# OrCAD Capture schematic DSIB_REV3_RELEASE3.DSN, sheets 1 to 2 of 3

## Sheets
1 Motor Driver: size Custom; rev: 3
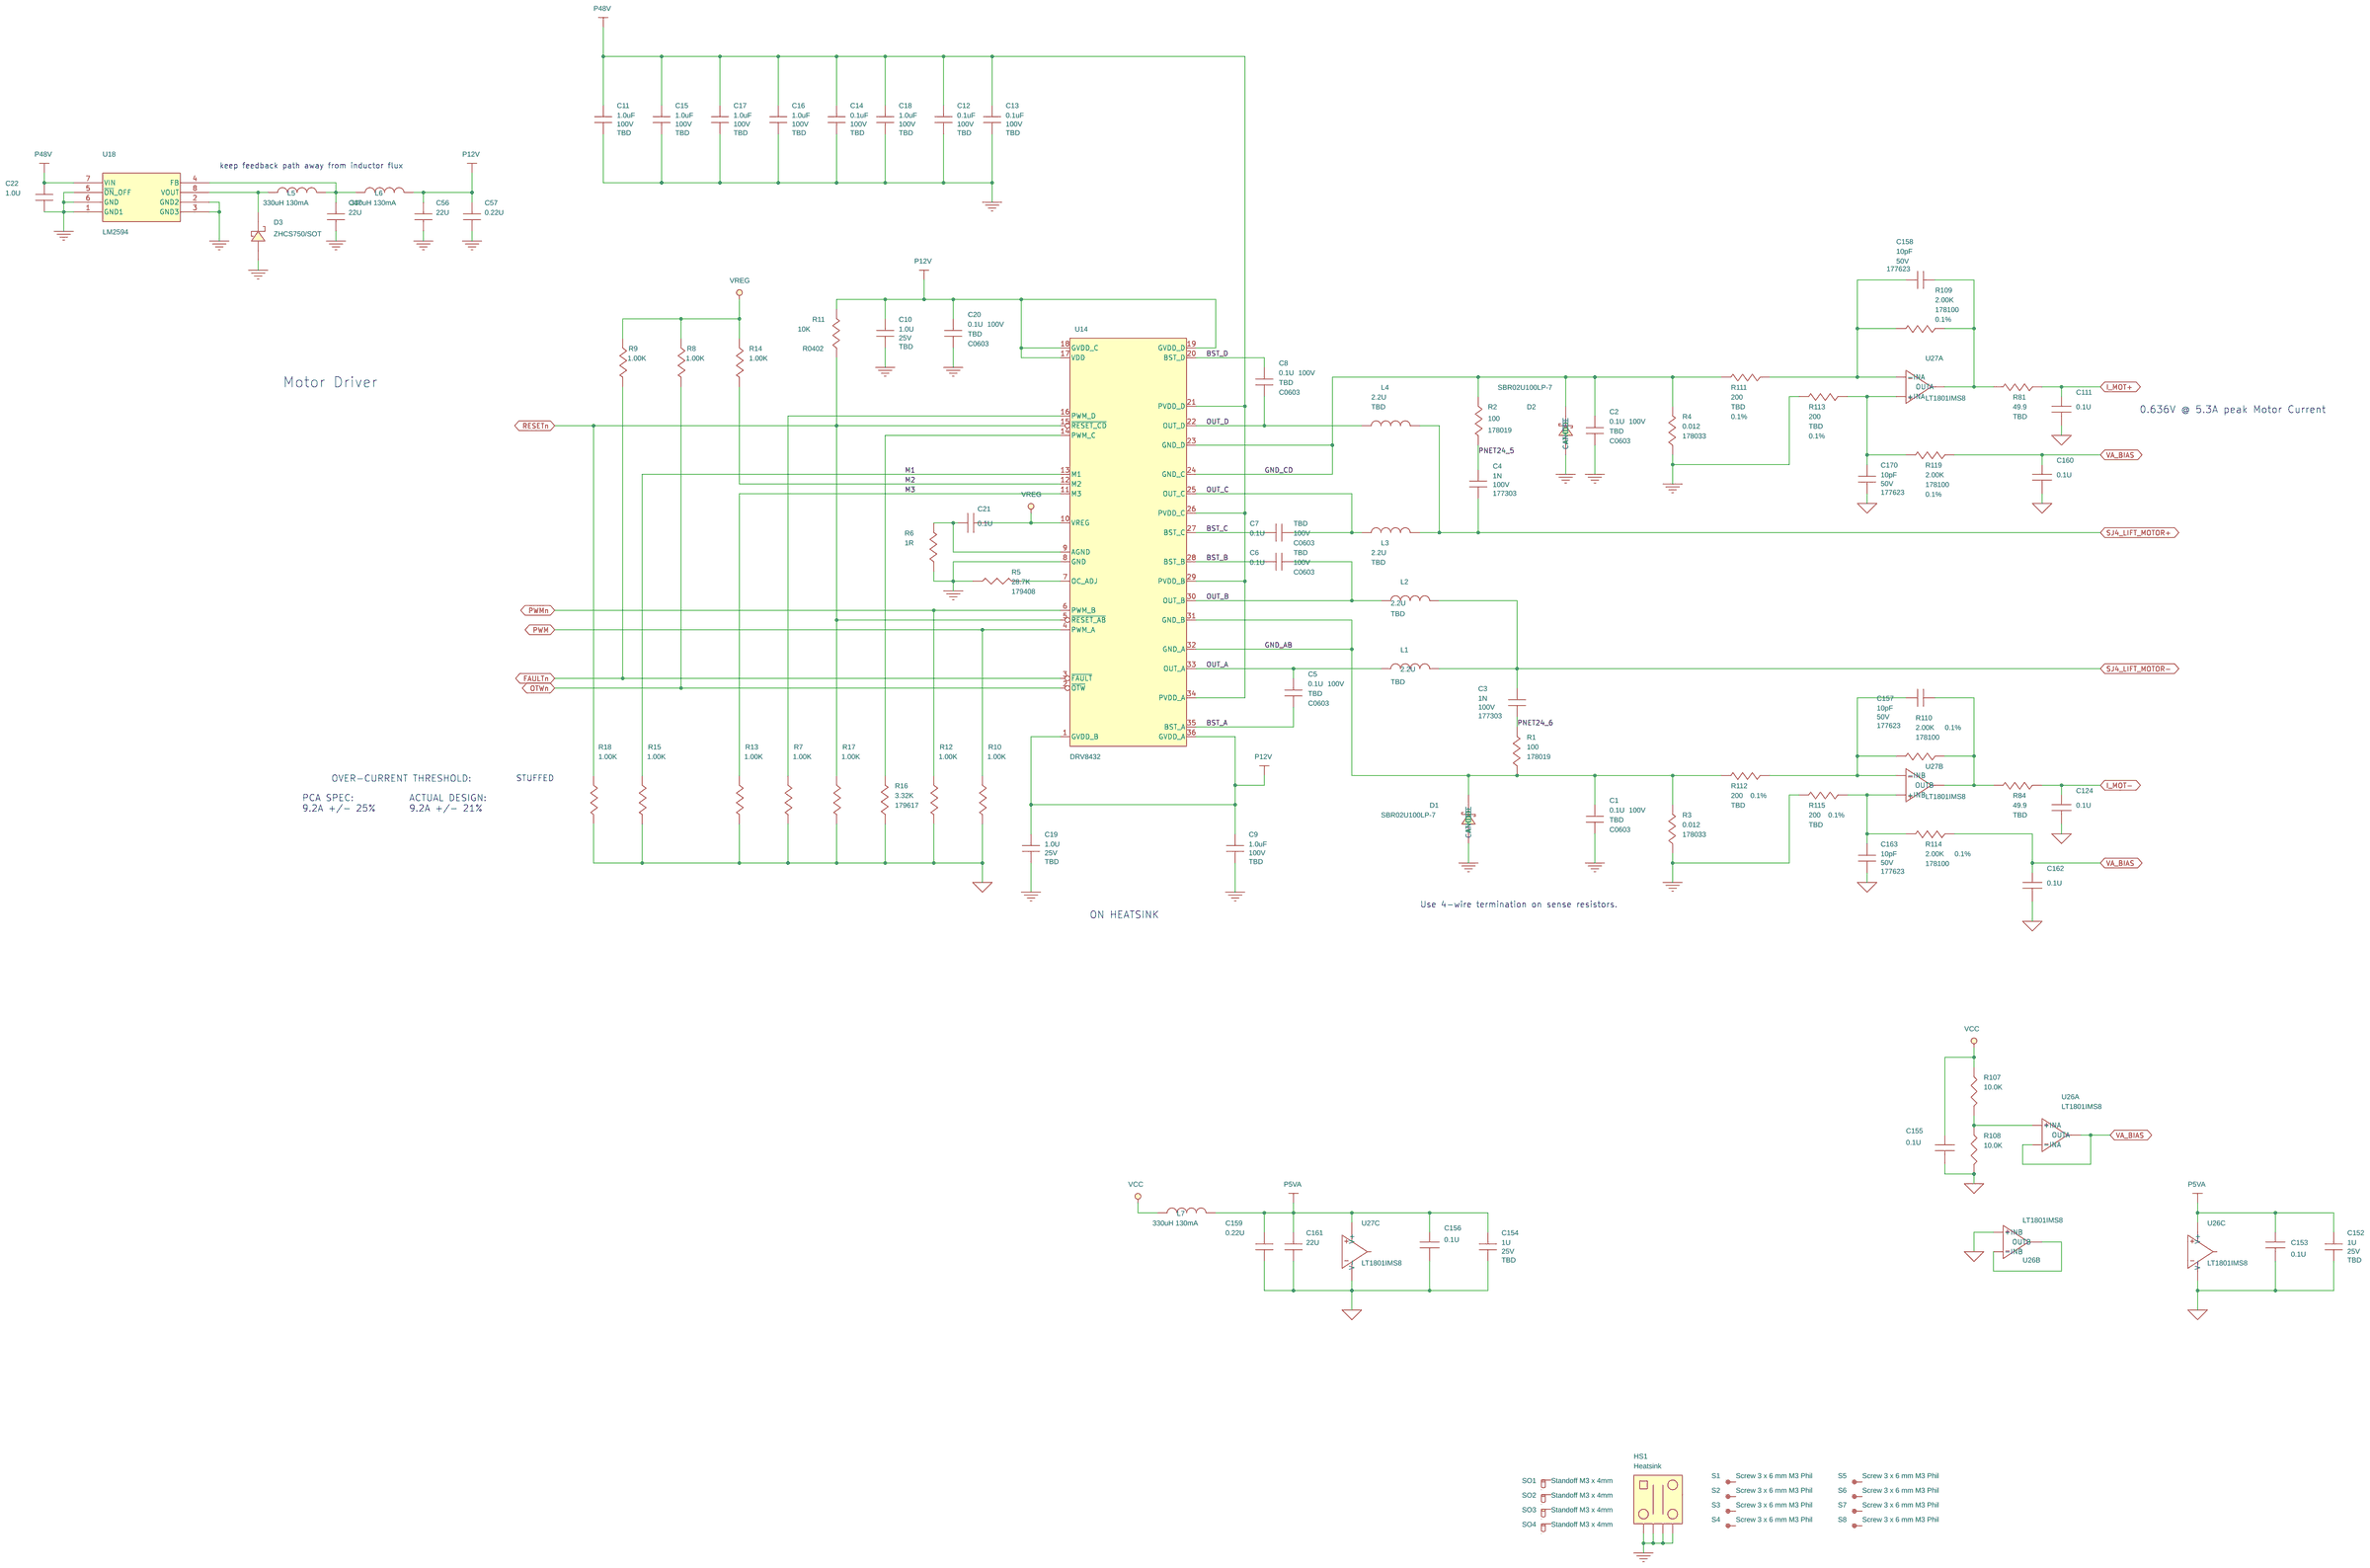
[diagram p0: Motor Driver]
2 Mux: size Custom
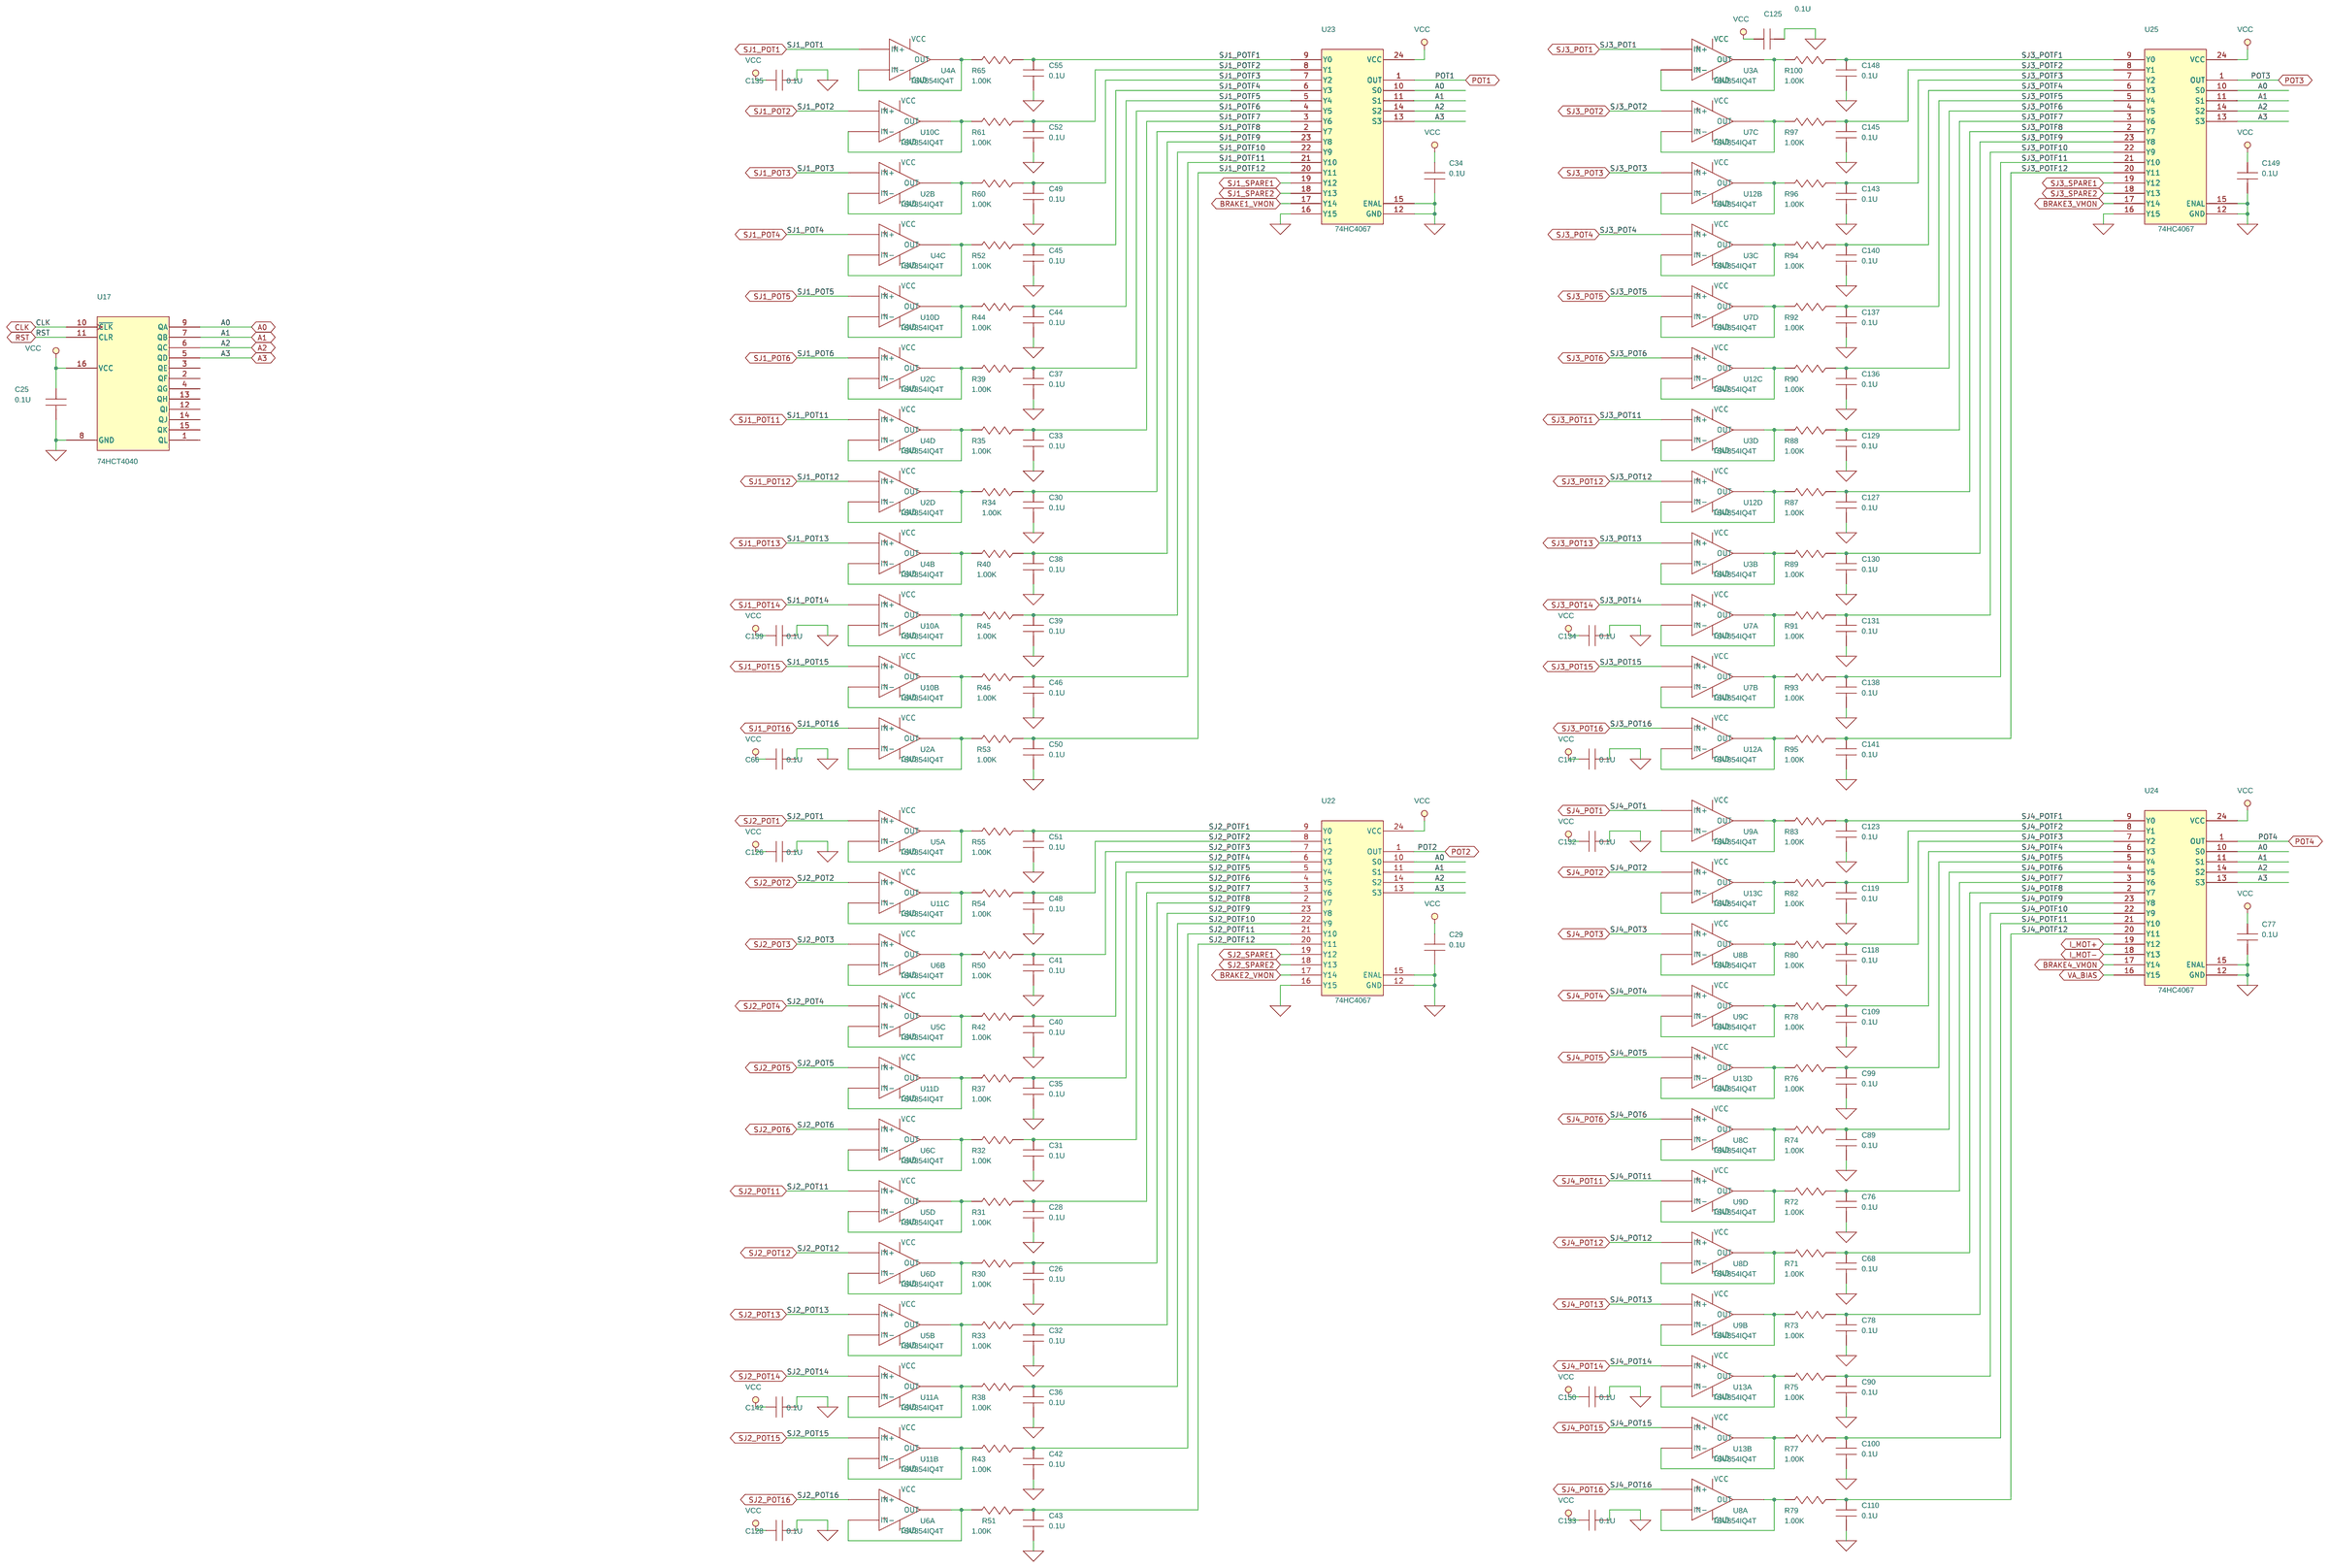
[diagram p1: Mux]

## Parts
sheet Motor Driver
C1  0.1U  [C0603]
C2  0.1U  [C0603]
C3  1N  [C0603]
C4  1N  [C0603]
C5  0.1U  [C0603]
C6  0.1U  [C0603]
C7  0.1U  [C0603]
C8  0.1U  [C0603]
C9  1.0uF  [C0805]
C10  1.0U  [C0603]
C11  1.0uF  [C0805]
C12  0.1uF  [C0805]
C13  0.1uF  [C0805]
C14  0.1uF  [C0805]
C15  1.0uF  [C0805]
C16  1.0uF  [C0805]
C17  1.0uF  [C0805]
C18  1.0uF  [C0805]
C19  1.0U  [C0603]
C20  0.1U  [C0603]
C21  0.1U  [C0402]
C22  1.0U  [C1210]
C47  22U  [C1210]
C56  22U  [C1210]
C57  0.22U  [C0603]
C111  0.1U  [C0402]
C124  0.1U  [C0402]
C152  1U  [CAPC1005_IS0402N]
C153  0.1U  [C0402]
C154  1U  [CAPC1005_IS0402N]
C155  0.1U  [C0402]
C156  0.1U  [C0402]
C157  10pF  [CAPC1005_IS0402N]
C158  10pF  [CAPC1005_IS0402N]
C159  0.22U  [C0603]
C160  0.1U  [C0402]
C161  22U  [C0603]
C162  0.1U  [C0402]
C163  10pF  [CAPC1005_IS0402N]
C170  10pF  [CAPC1005_IS0402N]
D1  SBR02U100LP-7  [DIOS2_173257]
D2  SBR02U100LP-7  [DIOS2_173257]
D3  ZHCS750/SOT  [SM/SOT23_123]
HS1  Heatsink  [HS_VHS45]
L1  2.2U  [INDS2_174036_LARGER]
L2  2.2U  [INDS2_174036_LARGER]
L3  2.2U  [INDS2_174036_LARGER]
L4  2.2U  [INDS2_174036_LARGER]
L5  330uH 130mA  [L4MMX4MM]
L6  330uH 130mA  [L4MMX4MM]
L7  330uH 130mA  [L4MMX4MM]
R1  100  [RESC3225_IS1210N]
R2  100  [RESC3225_IS1210N]
R3  0.012  [RESC3216_IS1206N]
R4  0.012  [RESC3216_IS1206N]
R5  28.7K  [R0402]
R6  1R  [R0402]
R7  1.00K  [RESC1005_IS0402N]
R8  1.00K  [RESC1005_IS0402N]
R9  1.00K  [RESC1005_IS0402N]
R10  1.00K  [RESC1005_IS0402N]
R11  10K  [R0402]
R12  1.00K  [RESC1005_IS0402N]
R13  1.00K  [RESC1005_IS0402N]
R14  1.00K  [RESC1005_IS0402N]
R15  1.00K  [RESC1005_IS0402N]
R16  3.32K  [RESC1005_IS0402N]
R17  1.00K  [RESC1005_IS0402N]
R18  1.00K  [RESC1005_IS0402N]
R81  49.9  [RESC1005_IS0402N]
R84  49.9  [RESC1005_IS0402N]
R107  10.0K  [R0402]
R108  10.0K  [R0402]
R109  2.00K  [RESC1005_IS0402N]
R110  2.00K  [RESC1005_IS0402N]
R111  200  [RESC1005_IS0402N]
R112  200  [RESC1005_IS0402N]
R113  200  [RESC1005_IS0402N]
R114  2.00K  [RESC1005_IS0402N]
R115  200  [RESC1005_IS0402N]
R119  2.00K  [RESC1005_IS0402N]
S1  Screw 3 x 6 mm M3 Phil  [TH825]
S2  Screw 3 x 6 mm M3 Phil  [TH825]
S3  Screw 3 x 6 mm M3 Phil  [TH825]
S4  Screw 3 x 6 mm M3 Phil  [TH825]
S5  Screw 3 x 6 mm M3 Phil  [TH825]
S6  Screw 3 x 6 mm M3 Phil  [TH825]
S7  Screw 3 x 6 mm M3 Phil  [TH825]
S8  Screw 3 x 6 mm M3 Phil  [TH825]
SO1  Standoff M3 x 4mm  [TH40Thou]
SO2  Standoff M3 x 4mm  [TH40Thou]
SO3  Standoff M3 x 4mm  [TH40Thou]
SO4  Standoff M3 x 4mm  [TH40Thou]
U14  DRV8432  [PDSO36]
U18  LM2594  [SO8]
U26  LT1801IMS8  [TSOP65P490_8_D300N]  (sections A,B,C)
U27  LT1801IMS8  [TSOP65P490_8_D300N]  (sections A,B,C)
sheet Mux
C25  0.1U  [C0402]
C26  0.1U  [C0402]
C28  0.1U  [C0402]
C29  0.1U  [C0402]
C30  0.1U  [C0402]
C31  0.1U  [C0402]
C32  0.1U  [C0402]
C33  0.1U  [C0402]
C34  0.1U  [C0402]
C35  0.1U  [C0402]
C36  0.1U  [C0402]
C37  0.1U  [C0402]
C38  0.1U  [C0402]
C39  0.1U  [C0402]
C40  0.1U  [C0402]
C41  0.1U  [C0402]
C42  0.1U  [C0402]
C43  0.1U  [C0402]
C44  0.1U  [C0402]
C45  0.1U  [C0402]
C46  0.1U  [C0402]
C48  0.1U  [C0402]
C49  0.1U  [C0402]
C50  0.1U  [C0402]
C51  0.1U  [C0402]
C52  0.1U  [C0402]
C55  0.1U  [C0402]
C66  0.1U  [C0402]
C68  0.1U  [C0402]
C76  0.1U  [C0402]
C77  0.1U  [C0402]
C78  0.1U  [C0402]
C89  0.1U  [C0402]
C90  0.1U  [C0402]
C99  0.1U  [C0402]
C100  0.1U  [C0402]
C109  0.1U  [C0402]
C110  0.1U  [C0402]
C118  0.1U  [C0402]
C119  0.1U  [C0402]
C123  0.1U  [C0402]
C125  0.1U  [C0402]
C126  0.1U  [C0402]
C127  0.1U  [C0402]
C128  0.1U  [C0402]
C129  0.1U  [C0402]
C130  0.1U  [C0402]
C131  0.1U  [C0402]
C132  0.1U  [C0402]
C133  0.1U  [C0402]
C134  0.1U  [C0402]
C135  0.1U  [C0402]
C136  0.1U  [C0402]
C137  0.1U  [C0402]
C138  0.1U  [C0402]
C139  0.1U  [C0402]
C140  0.1U  [C0402]
C141  0.1U  [C0402]
C142  0.1U  [C0402]
C143  0.1U  [C0402]
C145  0.1U  [C0402]
C147  0.1U  [C0402]
C148  0.1U  [C0402]
C149  0.1U  [C0402]
C150  0.1U  [C0402]
R30  1.00K  [RESC1005_IS0402N]
R31  1.00K  [RESC1005_IS0402N]
R32  1.00K  [RESC1005_IS0402N]
R33  1.00K  [RESC1005_IS0402N]
R34  1.00K  [RESC1005_IS0402N]
R35  1.00K  [RESC1005_IS0402N]
R37  1.00K  [RESC1005_IS0402N]
R38  1.00K  [RESC1005_IS0402N]
R39  1.00K  [RESC1005_IS0402N]
R40  1.00K  [RESC1005_IS0402N]
R42  1.00K  [RESC1005_IS0402N]
R43  1.00K  [RESC1005_IS0402N]
R44  1.00K  [RESC1005_IS0402N]
R45  1.00K  [RESC1005_IS0402N]
R46  1.00K  [RESC1005_IS0402N]
R50  1.00K  [RESC1005_IS0402N]
R51  1.00K  [RESC1005_IS0402N]
R52  1.00K  [RESC1005_IS0402N]
R53  1.00K  [RESC1005_IS0402N]
R54  1.00K  [RESC1005_IS0402N]
R55  1.00K  [RESC1005_IS0402N]
R60  1.00K  [RESC1005_IS0402N]
R61  1.00K  [RESC1005_IS0402N]
R65  1.00K  [RESC1005_IS0402N]
R71  1.00K  [RESC1005_IS0402N]
R72  1.00K  [RESC1005_IS0402N]
R73  1.00K  [RESC1005_IS0402N]
R74  1.00K  [RESC1005_IS0402N]
R75  1.00K  [RESC1005_IS0402N]
R76  1.00K  [RESC1005_IS0402N]
R77  1.00K  [RESC1005_IS0402N]
R78  1.00K  [RESC1005_IS0402N]
R79  1.00K  [RESC1005_IS0402N]
R80  1.00K  [RESC1005_IS0402N]
R82  1.00K  [RESC1005_IS0402N]
R83  1.00K  [RESC1005_IS0402N]
R87  1.00K  [RESC1005_IS0402N]
R88  1.00K  [RESC1005_IS0402N]
R89  1.00K  [RESC1005_IS0402N]
R90  1.00K  [RESC1005_IS0402N]
R91  1.00K  [RESC1005_IS0402N]
R92  1.00K  [RESC1005_IS0402N]
R93  1.00K  [RESC1005_IS0402N]
R94  1.00K  [RESC1005_IS0402N]
R95  1.00K  [RESC1005_IS0402N]
R96  1.00K  [RESC1005_IS0402N]
R97  1.00K  [RESC1005_IS0402N]
R100  1.00K  [RESC1005_IS0402N]
U2  TSV854IQ4T  [QFN16-0.5MM]  (sections A,B,C,D)
U3  TSV854IQ4T  [QFN16-0.5MM]  (sections A,B,C,D)
U4  TSV854IQ4T  [QFN16-0.5MM]  (sections A,B,C,D)
U5  TSV854IQ4T  [QFN16-0.5MM]  (sections A,B,C,D)
U6  TSV854IQ4T  [QFN16-0.5MM]  (sections A,B,C,D)
U7  TSV854IQ4T  [QFN16-0.5MM]  (sections A,B,C,D)
U8  TSV854IQ4T  [QFN16-0.5MM]  (sections A,B,C,D)
U9  TSV854IQ4T  [QFN16-0.5MM]  (sections A,B,C,D)
U10  TSV854IQ4T  [QFN16-0.5MM]  (sections A,B,C,D)
U11  TSV854IQ4T  [QFN16-0.5MM]  (sections A,B,C,D)
U12  TSV854IQ4T  [QFN16-0.5MM]  (sections A,B,C,D)
U13  TSV854IQ4T  [QFN16-0.5MM]  (sections A,B,C,D)
U17  74HCT4040  [TSSOP16]
U22  74HC4067  [DHVQFN24]
U23  74HC4067  [DHVQFN24]
U24  74HC4067  [DHVQFN24]
U25  74HC4067  [DHVQFN24]

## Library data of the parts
C1 C2 C5-C8 C20 = C_0.1F_100V_X7R_0603: COMPFIXED: NO; COMPGROUP: 0; COMPHEIGHT: 0.000; COMPKEY: NO; COMPLOC: [5705.000,3345.000]; COMPLOCKED: NO; COMPROT: 180; COMPSIDE: TOP; DECOUPLER: NO; ISI P/N: TBD; MEMORY: NO; ROOM: MOTOR1; Tolerance: 10%; Voltage: 100V
C3 C4 = C_1nF_10%_100V_X7R_0603_0: COMPFIXED: NO; COMPGROUP: 0; COMPHEIGHT: 0.000; COMPKEY: NO; COMPLOC: [6070.000,3280.000]; COMPLOCKED: NO; COMPROT: 180; COMPSIDE: TOP; DECOUPLER: NO; ISI P/N: 177303; MEMORY: NO; Tolerance: 10%; Voltage: 100V
C9 C11 C15-C18 = C_1uF_100V_X7R: COMPFIXED: NO; COMPGROUP: 0; COMPHEIGHT: 0.000; COMPKEY: NO; COMPLOC: [5820.000,2640.000]; COMPLOCKED: NO; COMPROT: 180; COMPSIDE: TOP; DECOUPLER: NO; FPLIST: C1206; ISI P/N: TBD; MEMORY: NO; ROOM: MOTOR1; Tolerance: 10%; Voltage: 100V
C10 C19 = C_1uF_25V_X7R_0603: COMPFIXED: NO; COMPGROUP: 0; COMPHEIGHT: 0.000; COMPKEY: NO; COMPLOC: [5896.000,2216.000]; COMPLOCKED: NO; COMPROT: 180; COMPSIDE: TOP; DECOUPLER: NO; ISI P/N: TBD; MEMORY: NO; ROOM: MOTOR1; Tolerance: 20%; Voltage: 25V
C12-C14 = C_0.1uF_100V_X7R_0805: COMPFIXED: NO; COMPGROUP: 0; COMPHEIGHT: 0.000; COMPKEY: NO; COMPLOC: [6555.000,2640.000]; COMPLOCKED: NO; COMPROT: 0; COMPSIDE: TOP; DECOUPLER: NO; FPLIST: CAPC2012_IS0805N; ISI P/N: TBD; MEMORY: NO; ROOM: MOTOR1; Tolerance: 10%; Voltage: 100V
C21 C26 C28 C30-C33 C35-C46 C48-C52 C55 C68 C76 C78 C89 C90 C99 C100 C109-C111 C118 C119 C123 C124 C127 C129-C131 C136-C138 C140 C141 C143 C145 C148 C153 C155 C156 C160 C162 = C_100nF_10%_50V_X7R_0: COMPFIXED: NO; COMPGROUP: 0; COMPHEIGHT: 0.000; COMPKEY: NO; COMPLOC: [6693.000,6327.000]; COMPLOCKED: NO; COMPROT: 180; COMPSIDE: BOT; DECOUPLER: NO; MEMORY: NO
C22 = C_1uF_10%_100V_X7R_1206: COMPFIXED: NO; COMPGROUP: 0; COMPHEIGHT: 0.000; COMPKEY: NO; COMPLOC: [7182.000,6396.000]; COMPLOCKED: NO; COMPROT: 0; COMPSIDE: BOT; DECOUPLER: NO; MEMORY: NO
C47 = C_22UF_20%_25V_X5R_1210: COMPFIXED: NO; COMPGROUP: 0; COMPHEIGHT: 0.000; COMPKEY: NO; COMPLOC: [7074.000,5796.000]; COMPLOCKED: NO; COMPROT: 180; COMPSIDE: BOT; DECOUPLER: NO; MEMORY: NO
C56 = C_22UF_20%_25V_X5R_1210: COMPFIXED: NO; COMPGROUP: 0; COMPHEIGHT: 0.000; COMPKEY: NO; COMPLOC: [6757.500,5713.500]; COMPLOCKED: NO; COMPROT: 90; COMPSIDE: BOT; DECOUPLER: NO; MEMORY: NO
C57 = C_220nF_10%_25V_X7R_0603: COMPFIXED: NO; COMPGROUP: 0; COMPHEIGHT: 0.000; COMPKEY: NO; COMPLOC: [6636.000,5670.000]; COMPLOCKED: NO; COMPROT: 90; COMPSIDE: BOT; DECOUPLER: NO; MEMORY: NO
C152 = C_1uF_25V_X5R_0402_1: COMPFIXED: NO; COMPGROUP: 0; COMPHEIGHT: 0.000; COMPKEY: NO; COMPLOC: [6042.000,3654.000]; COMPLOCKED: NO; COMPROT: 90; COMPSIDE: BOT; DECOUPLER: NO; FPLIST: capc1005_is0402n; ISI P/N: TBD; MEMORY: NO; ROOM: MOTOR1; Tolerance: 20%; Voltage: 25V
C154 = C_1uF_25V_X5R_0402_1: COMPFIXED: NO; COMPGROUP: 0; COMPHEIGHT: 0.000; COMPKEY: NO; COMPLOC: [5934.000,3654.000]; COMPLOCKED: NO; COMPROT: 90; COMPSIDE: BOT; DECOUPLER: NO; FPLIST: capc1005_is0402n; ISI P/N: TBD; MEMORY: NO; ROOM: MOTOR1; Tolerance: 20%; Voltage: 25V
C157 = C_10pF_50V_NPO_0402: COMPFIXED: NO; COMPGROUP: 0; COMPHEIGHT: 0.000; COMPKEY: NO; COMPLOC: [5933.000,3474.000]; COMPLOCKED: NO; COMPROT: 180; COMPSIDE: BOT; DECOUPLER: NO; FPLIST: capc1005_is0402n; ISI P/N: 177623; MEMORY: NO; Tolerance: 5%; Voltage: 50V
C158 = C_10pF_50V_NPO_0402: COMPFIXED: NO; COMPGROUP: 0; COMPHEIGHT: 0.000; COMPKEY: NO; COMPLOC: [6353.000,3444.000]; COMPLOCKED: NO; COMPROT: 180; COMPSIDE: BOT; DECOUPLER: NO; FPLIST: capc1005_is0402n; ISI P/N: 177623; MEMORY: NO; Tolerance: 5%; Voltage: 50V
C159 = C_220nF_10%_25V_X7R_0603: COMPFIXED: NO; COMPGROUP: 0; COMPHEIGHT: 0.000; COMPKEY: NO; COMPLOC: [5868.000,3390.000]; COMPLOCKED: NO; COMPROT: 0; COMPSIDE: BOT; DECOUPLER: NO; MEMORY: NO
C161 = C_22UF_20%_10V_X5R_0: COMPFIXED: NO; COMPGROUP: 0; COMPHEIGHT: 0.000; COMPKEY: NO; COMPLOC: [5868.000,3318.000]; COMPLOCKED: NO; COMPROT: 0; COMPSIDE: BOT; DECOUPLER: NO; FPLIST: C1210; MEMORY: NO
C163 = C_10pF_50V_NPO_0402: COMPFIXED: NO; COMPGROUP: 0; COMPHEIGHT: 0.000; COMPKEY: NO; COMPLOC: [6084.000,3228.000]; COMPLOCKED: NO; COMPROT: 180; COMPSIDE: BOT; DECOUPLER: NO; FPLIST: capc1005_is0402n; ISI P/N: 177623; MEMORY: NO; Tolerance: 5%; Voltage: 50V
C170 = C_10pF_50V_NPO_0402: COMPFIXED: NO; COMPGROUP: 0; COMPHEIGHT: 0.000; COMPKEY: NO; COMPLOC: [6356.000,3171.000]; COMPLOCKED: NO; COMPROT: 180; COMPSIDE: BOT; DECOUPLER: NO; FPLIST: capc1005_is0402n; ISI P/N: 177623; MEMORY: NO; Tolerance: 5%; Voltage: 50V
D1 = TMP_131458: COMPFIXED: NO; COMPGROUP: 0; COMPHEIGHT: 0.000; COMPKEY: NO; COMPLOC: [5680.000,3275.000]; COMPLOCKED: NO; COMPROT: 180; COMPSIDE: TOP; DECOUPLER: NO; MEMORY: NO; ROOM: MOTOR1
D2 = TMP_131458: COMPFIXED: NO; COMPGROUP: 0; COMPHEIGHT: 0.000; COMPKEY: NO; COMPLOC: [6690.000,3275.000]; COMPLOCKED: NO; COMPROT: 0; COMPSIDE: TOP; DECOUPLER: NO; MEMORY: NO; ROOM: MOTOR1
D3 = ZHCS750_SOT_1: COMPFIXED: NO; COMPGROUP: 0; COMPHEIGHT: 0.000; COMPKEY: NO; COMPLOC: [6972.000,5670.000]; COMPLOCKED: NO; COMPROT: 0; COMPSIDE: BOT; DECOUPLER: NO; MEMORY: NO
HS1 = Heat_Sink_2: COMPFIXED: YES; COMPGROUP: 0; COMPHEIGHT: 0.000; COMPKEY: NO; COMPLOC: [5256.000,3498.000]; COMPLOCKED: YES; COMPROT: 270; COMPSIDE: TOP; DECOUPLER: NO; MEMORY: NO
L1 = INDUCTOR_1: COMPFIXED: NO; COMPGROUP: 0; COMPHEIGHT: 0.000; COMPKEY: NO; COMPLOC: [5620.000,2995.000]; COMPLOCKED: NO; COMPROT: 90; COMPSIDE: TOP; DECOUPLER: NO; FPLIST: INDS2_174063_REV1,INDS2_174063; ISI P/N: TBD; MEMORY: NO; Tolerance: 20%
L2 = INDUCTOR_1: COMPFIXED: NO; COMPGROUP: 0; COMPHEIGHT: 0.000; COMPKEY: NO; COMPLOC: [6030.000,2995.000]; COMPLOCKED: NO; COMPROT: 90; COMPSIDE: TOP; DECOUPLER: NO; FPLIST: INDS2_174063_REV1,INDS2_174063; ISI P/N: TBD; MEMORY: NO; Tolerance: 20%
L3 = INDUCTOR_1: COMPFIXED: NO; COMPGROUP: 0; COMPHEIGHT: 0.000; COMPKEY: NO; COMPLOC: [6335.000,2995.000]; COMPLOCKED: NO; COMPROT: 90; COMPSIDE: TOP; DECOUPLER: NO; FPLIST: INDS2_174063_REV1,INDS2_174063; ISI P/N: TBD; MEMORY: NO; Tolerance: 20%
L4 = INDUCTOR_1: COMPFIXED: NO; COMPGROUP: 0; COMPHEIGHT: 0.000; COMPKEY: NO; COMPLOC: [6745.000,2995.000]; COMPLOCKED: NO; COMPROT: 90; COMPSIDE: TOP; DECOUPLER: NO; FPLIST: INDS2_174063_REV1,INDS2_174063; ISI P/N: TBD; MEMORY: NO; Tolerance: 20%
L5-L7 = L_330uH_130mA_SMT_0: COMPFIXED: NO; COMPGROUP: 0; COMPHEIGHT: 0.000; COMPKEY: NO; COMPLOC: [6930.933,5820.950]; COMPLOCKED: NO; COMPROT: 270; COMPSIDE: BOT; DECOUPLER: NO; MEMORY: NO
R1 = R_100R_5%_1210: COMPFIXED: NO; COMPGROUP: 0; COMPHEIGHT: 0.000; COMPKEY: NO; COMPLOC: [5925.000,3315.000]; COMPLOCKED: NO; COMPROT: 180; COMPSIDE: TOP; DECOUPLER: NO; ISI P/N: 178019; MEMORY: NO; Power: 1/4W; ROOM: MOTOR1; Tolerance: 1%
R2 = R_100R_5%_1210: COMPFIXED: NO; COMPGROUP: 0; COMPHEIGHT: 0.000; COMPKEY: NO; COMPLOC: [6450.000,3310.000]; COMPLOCKED: NO; COMPROT: 0; COMPSIDE: TOP; DECOUPLER: NO; ISI P/N: 178019; MEMORY: NO; Power: 1/4W; ROOM: MOTOR1; Tolerance: 1%
R3 = R_0.012R_1%_1206: COMPFIXED: NO; COMPGROUP: 0; COMPHEIGHT: 0.000; COMPKEY: NO; COMPLOC: [5825.000,3055.000]; COMPLOCKED: NO; COMPROT: 90; COMPSIDE: TOP; DECOUPLER: NO; ISI P/N: 178033; MEMORY: NO; Power: 1/2W; Tolerance: 1%
R4 = R_0.012R_1%_1206: COMPFIXED: NO; COMPGROUP: 0; COMPHEIGHT: 0.000; COMPKEY: NO; COMPLOC: [6540.000,2965.000]; COMPLOCKED: NO; COMPROT: 90; COMPSIDE: TOP; DECOUPLER: NO; ISI P/N: 178033; MEMORY: NO; Power: 1/2W; Tolerance: 1%
R5 = R_28.7K_1%_TF_0402: COMPFIXED: NO; COMPGROUP: 0; COMPHEIGHT: 0.000; COMPKEY: NO; COMPLOC: [6114.000,2106.000]; COMPLOCKED: NO; COMPROT: 90; COMPSIDE: TOP; DECOUPLER: NO; FPLIST: RESC1608_IS0603N; ISI P/N: 179408; MEMORY: NO
R6 = R_1R_1%_TF: COMPFIXED: NO; COMPGROUP: 0; COMPHEIGHT: 0.000; COMPKEY: NO; COMPLOC: [6168.000,2148.000]; COMPLOCKED: NO; COMPROT: 270; COMPSIDE: TOP; DECOUPLER: NO; MEMORY: NO
R7 = R1K1%0402_0: COMPFIXED: NO; COMPGROUP: 0; COMPHEIGHT: 0.000; COMPKEY: NO; COMPLOC: [6492.000,2115.000]; COMPLOCKED: NO; COMPROT: 180; COMPSIDE: TOP; DECOUPLER: NO; MEMORY: NO
R8 = R1K1%0402_0: COMPFIXED: NO; COMPGROUP: 0; COMPHEIGHT: 0.000; COMPKEY: NO; COMPLOC: [5886.000,2052.000]; COMPLOCKED: NO; COMPROT: 270; COMPSIDE: TOP; DECOUPLER: NO; MEMORY: NO
R9 = R1K1%0402_0: COMPFIXED: NO; COMPGROUP: 0; COMPHEIGHT: 0.000; COMPKEY: NO; COMPLOC: [5940.000,2052.000]; COMPLOCKED: NO; COMPROT: 270; COMPSIDE: TOP; DECOUPLER: NO; MEMORY: NO
R10 = R1K1%0402_0: COMPFIXED: NO; COMPGROUP: 0; COMPHEIGHT: 0.000; COMPKEY: NO; COMPLOC: [5995.000,2008.000]; COMPLOCKED: NO; COMPROT: 90; COMPSIDE: TOP; DECOUPLER: NO; MEMORY: NO
R11 = R10.0K1%0402_0: COMPFIXED: NO; COMPGROUP: 0; COMPHEIGHT: 0.000; COMPKEY: NO; COMPLOC: [2058.000,5802.000]; COMPLOCKED: NO; COMPROT: 180; COMPSIDE: BOT; DECOUPLER: NO; MEMORY: NO
R12 = R1K1%0402_0: COMPFIXED: NO; COMPGROUP: 0; COMPHEIGHT: 0.000; COMPKEY: NO; COMPLOC: [6105.000,2008.000]; COMPLOCKED: NO; COMPROT: 90; COMPSIDE: TOP; DECOUPLER: NO; MEMORY: NO
R13 = R1K1%0402_0: COMPFIXED: NO; COMPGROUP: 0; COMPHEIGHT: 0.000; COMPKEY: NO; COMPLOC: [6265.000,2008.000]; COMPLOCKED: NO; COMPROT: 90; COMPSIDE: TOP; DECOUPLER: NO; MEMORY: NO
R14 = R1K1%0402_0: COMPFIXED: NO; COMPGROUP: 0; COMPHEIGHT: 0.000; COMPKEY: NO; COMPLOC: [6318.000,2052.000]; COMPLOCKED: NO; COMPROT: 270; COMPSIDE: TOP; DECOUPLER: NO; MEMORY: NO
R15 = R1K1%0402_0: COMPFIXED: NO; COMPGROUP: 0; COMPHEIGHT: 0.000; COMPKEY: NO; COMPLOC: [6375.000,2008.000]; COMPLOCKED: NO; COMPROT: 90; COMPSIDE: TOP; DECOUPLER: NO; MEMORY: NO
R16 = R_3.32K_1%_0402: COMPFIXED: NO; COMPGROUP: 0; COMPHEIGHT: 0.000; COMPKEY: NO; COMPLOC: [6426.000,2052.000]; COMPLOCKED: NO; COMPROT: 270; COMPSIDE: TOP; DECOUPLER: NO; FPLIST: resc1005_is0402n; ISI P/N: 179617; MEMORY: NO; Power: 1/16W; Tolerance: 1%
R17 = R1K1%0402_0: COMPFIXED: NO; COMPGROUP: 0; COMPHEIGHT: 0.000; COMPKEY: NO; COMPLOC: [6480.000,2008.000]; COMPLOCKED: NO; COMPROT: 90; COMPSIDE: TOP; DECOUPLER: NO; MEMORY: NO
R18 = R1K1%0402_0: COMPFIXED: NO; COMPGROUP: 0; COMPHEIGHT: 0.000; COMPKEY: NO; COMPLOC: [6535.000,2008.000]; COMPLOCKED: NO; COMPROT: 90; COMPSIDE: TOP; DECOUPLER: NO; MEMORY: NO
R81 R84 = R49R1%0402_0: COMPFIXED: NO; COMPGROUP: 0; COMPHEIGHT: 0.000; COMPKEY: NO; COMPLOC: [5376.000,4668.000]; COMPLOCKED: NO; COMPROT: 180; COMPSIDE: BOT; DECOUPLER: NO; FPLIST: resc1005_is0402n; ISI P/N: TBD; MEMORY: NO; Power: 1/16W; Tolerance: 1%
R107 = R_10K_1%_TF_0402: COMPFIXED: NO; COMPGROUP: 0; COMPHEIGHT: 0.000; COMPKEY: NO; COMPLOC: [6408.000,3558.000]; COMPLOCKED: NO; COMPROT: 270; COMPSIDE: BOT; DECOUPLER: NO; MEMORY: NO
R108 = R_10K_1%_TF_0402: COMPFIXED: NO; COMPGROUP: 0; COMPHEIGHT: 0.000; COMPKEY: NO; COMPLOC: [6351.000,3603.000]; COMPLOCKED: NO; COMPROT: 90; COMPSIDE: BOT; DECOUPLER: NO; MEMORY: NO
R109 = R_200R_1%_0402_0: COMPFIXED: NO; COMPGROUP: 0; COMPHEIGHT: 0.000; COMPKEY: NO; COMPLOC: [6353.000,3390.000]; COMPLOCKED: NO; COMPROT: 180; COMPSIDE: BOT; DECOUPLER: NO; FPLIST: resc1005_is0402n; ISI P/N: 178100; MEMORY: NO; Power: 0.063W, 1/16W; Tolerance: 0.1%
R110 = R_200R_1%_0402_0: COMPFIXED: NO; COMPGROUP: 0; COMPHEIGHT: 0.000; COMPKEY: NO; COMPLOC: [5933.000,3420.000]; COMPLOCKED: NO; COMPROT: 180; COMPSIDE: BOT; DECOUPLER: NO; FPLIST: resc1005_is0402n; ISI P/N: 178100; MEMORY: NO; Power: 0.063W, 1/16W; Tolerance: 0.1%
R111 = R_200R_1%_0402_0: COMPFIXED: NO; COMPGROUP: 0; COMPHEIGHT: 0.000; COMPKEY: NO; COMPLOC: [6397.000,3336.000]; COMPLOCKED: NO; COMPROT: 0; COMPSIDE: BOT; DECOUPLER: NO; FPLIST: resc1005_is0402n; ISI P/N: TBD; MEMORY: NO; Power: 1/16W; Tolerance: 0.1%
R112 = R_200R_1%_0402_0: COMPFIXED: NO; COMPGROUP: 0; COMPHEIGHT: 0.000; COMPKEY: NO; COMPLOC: [5933.000,3366.000]; COMPLOCKED: NO; COMPROT: 180; COMPSIDE: BOT; DECOUPLER: NO; FPLIST: resc1005_is0402n; ISI P/N: TBD; MEMORY: NO; Power: 1/16W; Tolerance: 0.1%
R113 = R_200R_1%_0402_0: COMPFIXED: NO; COMPGROUP: 0; COMPHEIGHT: 0.000; COMPKEY: NO; COMPLOC: [6397.000,3282.000]; COMPLOCKED: NO; COMPROT: 0; COMPSIDE: BOT; DECOUPLER: NO; FPLIST: resc1005_is0402n; ISI P/N: TBD; MEMORY: NO; Power: 1/16W; Tolerance: 0.1%
R114 = R_200R_1%_0402_0: COMPFIXED: NO; COMPGROUP: 0; COMPHEIGHT: 0.000; COMPKEY: NO; COMPLOC: [6126.000,3282.000]; COMPLOCKED: NO; COMPROT: 0; COMPSIDE: BOT; DECOUPLER: NO; FPLIST: resc1005_is0402n; ISI P/N: 178100; MEMORY: NO; Power: 0.063W, 1/16W; Tolerance: 0.1%
R115 = R_200R_1%_0402_0: COMPFIXED: NO; COMPGROUP: 0; COMPHEIGHT: 0.000; COMPKEY: NO; COMPLOC: [5976.000,3244.000]; COMPLOCKED: NO; COMPROT: 270; COMPSIDE: BOT; DECOUPLER: NO; FPLIST: resc1005_is0402n; ISI P/N: TBD; MEMORY: NO; Power: 1/16W; Tolerance: 0.1%
R119 = R_200R_1%_0402_0: COMPFIXED: NO; COMPGROUP: 0; COMPHEIGHT: 0.000; COMPKEY: NO; COMPLOC: [6397.000,3228.000]; COMPLOCKED: NO; COMPROT: 0; COMPSIDE: BOT; DECOUPLER: NO; FPLIST: resc1005_is0402n; ISI P/N: 178100; MEMORY: NO; Power: 0.063W, 1/16W; Tolerance: 0.1%
S1-S8 = M3_1
SO1-SO4 = StandOff_0
U14 = TMP_151804: COMPFIXED: YES; COMPGROUP: 0; COMPHEIGHT: 0.000; COMPKEY: NO; COMPLOC: [5964.000,2214.000]; COMPLOCKED: NO; COMPROT: 0; COMPSIDE: TOP; DECOUPLER: NO; MEMORY: NO
U18 = LM2594HV_2: COMPFIXED: NO; COMPGROUP: 0; COMPHEIGHT: 0.000; COMPKEY: NO; COMPLOC: [7206.000,5946.000]; COMPLOCKED: NO; COMPROT: 0; COMPSIDE: BOT; DECOUPLER: NO; MEMORY: NO
U26 = U_LT1801_MSOP8: COMPFIXED: NO; COMPGROUP: 0; COMPHEIGHT: 0.000; COMPKEY: NO; COMPLOC: [6285.000,3663.000]; COMPLOCKED: NO; COMPROT: 90; COMPSIDE: BOT; DECOUPLER: NO; MEMORY: NO
U27 = U_LT1801_MSOP8: COMPFIXED: NO; COMPGROUP: 0; COMPHEIGHT: 0.000; COMPKEY: NO; COMPLOC: [6259.283,3426.000]; COMPLOCKED: NO; COMPROT: 90; COMPSIDE: BOT; DECOUPLER: NO; MEMORY: NO
C25 = C_100nF_10%_50V_X7R_0: COMPFIXED: NO; COMPGROUP: 0; COMPHEIGHT: 0.000; COMPKEY: NO; COMPLOC: [1746.000,6156.000]; COMPLOCKED: NO; COMPROT: 270; COMPSIDE: BOT; DECOUPLER: NO; MEMORY: NO
C29 = C_100nF_10%_50V_X7R_0: COMPFIXED: NO; COMPGROUP: 0; COMPHEIGHT: 0.000; COMPKEY: NO; COMPLOC: [2304.000,6057.000]; COMPLOCKED: NO; COMPROT: 180; COMPSIDE: BOT; DECOUPLER: NO; MEMORY: NO
C34 = C_100nF_10%_50V_X7R_0: COMPFIXED: NO; COMPGROUP: 0; COMPHEIGHT: 0.000; COMPKEY: NO; COMPLOC: [1032.000,6003.000]; COMPLOCKED: NO; COMPROT: 180; COMPSIDE: BOT; DECOUPLER: NO; MEMORY: NO
C66 = C_100nF_10%_50V_X7R_0: COMPFIXED: NO; COMPGROUP: 0; COMPHEIGHT: 0.000; COMPKEY: NO; COMPLOC: [780.000,5214.000]; COMPLOCKED: NO; COMPROT: 0; COMPSIDE: BOT; DECOUPLER: NO; MEMORY: NO
C77 = C_100nF_10%_50V_X7R_0: COMPFIXED: NO; COMPGROUP: 0; COMPHEIGHT: 0.000; COMPKEY: NO; COMPLOC: [5634.267,4949.733]; COMPLOCKED: NO; COMPROT: 180; COMPSIDE: BOT; DECOUPLER: NO; MEMORY: NO
C125 = C_100nF_10%_50V_X7R_0: COMPFIXED: NO; COMPGROUP: 0; COMPHEIGHT: 0.000; COMPKEY: NO; COMPLOC: [3840.000,4476.000]; COMPLOCKED: NO; COMPROT: 90; COMPSIDE: BOT; DECOUPLER: NO; MEMORY: NO
C126 = C_100nF_10%_50V_X7R_0: COMPFIXED: NO; COMPGROUP: 0; COMPHEIGHT: 0.000; COMPKEY: NO; COMPLOC: [1608.000,4422.000]; COMPLOCKED: NO; COMPROT: 180; COMPSIDE: BOT; DECOUPLER: NO; MEMORY: NO
C128 = C_100nF_10%_50V_X7R_0: COMPFIXED: NO; COMPGROUP: 0; COMPHEIGHT: 0.000; COMPKEY: NO; COMPLOC: [2805.000,4365.000]; COMPLOCKED: NO; COMPROT: 90; COMPSIDE: BOT; DECOUPLER: NO; MEMORY: NO
C132 = C_100nF_10%_50V_X7R_0: COMPFIXED: NO; COMPGROUP: 0; COMPHEIGHT: 0.000; COMPKEY: NO; COMPLOC: [5304.000,4332.000]; COMPLOCKED: NO; COMPROT: 180; COMPSIDE: BOT; DECOUPLER: NO; MEMORY: NO
C133 = C_100nF_10%_50V_X7R_0: COMPFIXED: NO; COMPGROUP: 0; COMPHEIGHT: 0.000; COMPKEY: NO; COMPLOC: [5094.000,4308.000]; COMPLOCKED: NO; COMPROT: 0; COMPSIDE: BOT; DECOUPLER: NO; MEMORY: NO
C134 = C_100nF_10%_50V_X7R_0: COMPFIXED: NO; COMPGROUP: 0; COMPHEIGHT: 0.000; COMPKEY: NO; COMPLOC: [4008.000,4326.000]; COMPLOCKED: NO; COMPROT: 0; COMPSIDE: BOT; DECOUPLER: NO; MEMORY: NO
C135 = C_100nF_10%_50V_X7R_0: COMPFIXED: NO; COMPGROUP: 0; COMPHEIGHT: 0.000; COMPKEY: NO; COMPLOC: [597.000,4329.000]; COMPLOCKED: NO; COMPROT: 90; COMPSIDE: BOT; DECOUPLER: NO; MEMORY: NO
C139 = C_100nF_10%_50V_X7R_0: COMPFIXED: NO; COMPGROUP: 0; COMPHEIGHT: 0.000; COMPKEY: NO; COMPLOC: [1716.000,4278.000]; COMPLOCKED: NO; COMPROT: 180; COMPSIDE: BOT; DECOUPLER: NO; MEMORY: NO
C142 = C_100nF_10%_50V_X7R_0: COMPFIXED: NO; COMPGROUP: 0; COMPHEIGHT: 0.000; COMPKEY: NO; COMPLOC: [2916.000,4182.000]; COMPLOCKED: NO; COMPROT: 180; COMPSIDE: BOT; DECOUPLER: NO; MEMORY: NO
C147 = C_100nF_10%_50V_X7R_0: COMPFIXED: NO; COMPGROUP: 0; COMPHEIGHT: 0.000; COMPKEY: NO; COMPLOC: [4002.000,4038.000]; COMPLOCKED: NO; COMPROT: 180; COMPSIDE: BOT; DECOUPLER: NO; MEMORY: NO
C149 = C_100nF_10%_50V_X7R_0: COMPFIXED: NO; COMPGROUP: 0; COMPHEIGHT: 0.000; COMPKEY: NO; COMPLOC: [5802.000,4026.000]; COMPLOCKED: NO; COMPROT: 180; COMPSIDE: BOT; DECOUPLER: NO; MEMORY: NO
C150 = C_100nF_10%_50V_X7R_0: COMPFIXED: NO; COMPGROUP: 0; COMPHEIGHT: 0.000; COMPKEY: NO; COMPLOC: [5100.000,4002.000]; COMPLOCKED: NO; COMPROT: 0; COMPSIDE: BOT; DECOUPLER: NO; MEMORY: NO
R30 = R1K1%0402_0: COMPFIXED: NO; COMPGROUP: 0; COMPHEIGHT: 0.000; COMPKEY: NO; COMPLOC: [2688.000,6120.000]; COMPLOCKED: NO; COMPROT: 0; COMPSIDE: BOT; DECOUPLER: NO; FPLIST: R0402; MEMORY: NO
R31 = R1K1%0402_0: COMPFIXED: NO; COMPGROUP: 0; COMPHEIGHT: 0.000; COMPKEY: NO; COMPLOC: [2688.000,6066.000]; COMPLOCKED: NO; COMPROT: 0; COMPSIDE: BOT; DECOUPLER: NO; FPLIST: R0402; MEMORY: NO
R32 = R1K1%0402_0: COMPFIXED: NO; COMPGROUP: 0; COMPHEIGHT: 0.000; COMPKEY: NO; COMPLOC: [2688.000,6012.000]; COMPLOCKED: NO; COMPROT: 0; COMPSIDE: BOT; DECOUPLER: NO; FPLIST: R0402; MEMORY: NO
R33 = R1K1%0402_0: COMPFIXED: NO; COMPGROUP: 0; COMPHEIGHT: 0.000; COMPKEY: NO; COMPLOC: [1962.000,6018.000]; COMPLOCKED: NO; COMPROT: 180; COMPSIDE: BOT; DECOUPLER: NO; FPLIST: R0402; MEMORY: NO
R34 = R1K1%0402_0: COMPFIXED: NO; COMPGROUP: 0; COMPHEIGHT: 0.000; COMPKEY: NO; COMPLOC: [1350.000,6066.000]; COMPLOCKED: NO; COMPROT: 0; COMPSIDE: BOT; DECOUPLER: NO; FPLIST: R0402; MEMORY: NO
R35 R39 R44 R52 R55 R60 R61 R65 = R1K1%0402_0: COMPFIXED: NO; COMPGROUP: 0; COMPHEIGHT: 0.000; COMPKEY: NO; COMPLOC: [2688.000,5748.000]; COMPLOCKED: NO; COMPROT: 0; COMPSIDE: BOT; DECOUPLER: NO; FPLIST: R0402; MEMORY: NO
R37 = R1K1%0402_0: COMPFIXED: NO; COMPGROUP: 0; COMPHEIGHT: 0.000; COMPKEY: NO; COMPLOC: [2688.000,5964.000]; COMPLOCKED: NO; COMPROT: 0; COMPSIDE: BOT; DECOUPLER: NO; FPLIST: R0402; MEMORY: NO
R38 = R1K1%0402_0: COMPFIXED: NO; COMPGROUP: 0; COMPHEIGHT: 0.000; COMPKEY: NO; COMPLOC: [1962.000,5964.000]; COMPLOCKED: NO; COMPROT: 180; COMPSIDE: BOT; DECOUPLER: NO; FPLIST: R0402; MEMORY: NO
R40 R45 R46 R53 = R1K1%0402_0: COMPFIXED: NO; COMPGROUP: 0; COMPHEIGHT: 0.000; COMPKEY: NO; COMPLOC: [786.000,5988.000]; COMPLOCKED: NO; COMPROT: 180; COMPSIDE: BOT; DECOUPLER: NO; FPLIST: R0402; MEMORY: NO
R42 = R1K1%0402_0: COMPFIXED: NO; COMPGROUP: 0; COMPHEIGHT: 0.000; COMPKEY: NO; COMPLOC: [2688.000,5910.000]; COMPLOCKED: NO; COMPROT: 0; COMPSIDE: BOT; DECOUPLER: NO; FPLIST: R0402; MEMORY: NO
R43 = R1K1%0402_0: COMPFIXED: NO; COMPGROUP: 0; COMPHEIGHT: 0.000; COMPKEY: NO; COMPLOC: [1962.000,5910.000]; COMPLOCKED: NO; COMPROT: 180; COMPSIDE: BOT; DECOUPLER: NO; FPLIST: R0402; MEMORY: NO
R50 = R1K1%0402_0: COMPFIXED: NO; COMPGROUP: 0; COMPHEIGHT: 0.000; COMPKEY: NO; COMPLOC: [2688.000,5856.000]; COMPLOCKED: NO; COMPROT: 0; COMPSIDE: BOT; DECOUPLER: NO; FPLIST: R0402; MEMORY: NO
R51 = R1K1%0402_0: COMPFIXED: NO; COMPGROUP: 0; COMPHEIGHT: 0.000; COMPKEY: NO; COMPLOC: [1962.000,5856.000]; COMPLOCKED: NO; COMPROT: 180; COMPSIDE: BOT; DECOUPLER: NO; FPLIST: R0402; MEMORY: NO
R54 = R1K1%0402_0: COMPFIXED: NO; COMPGROUP: 0; COMPHEIGHT: 0.000; COMPKEY: NO; COMPLOC: [2688.000,5802.000]; COMPLOCKED: NO; COMPROT: 0; COMPSIDE: BOT; DECOUPLER: NO; FPLIST: R0402; MEMORY: NO
R71 = R1K1%0402_0: COMPFIXED: NO; COMPGROUP: 0; COMPHEIGHT: 0.000; COMPKEY: NO; COMPLOC: [6042.000,4986.000]; COMPLOCKED: NO; COMPROT: 0; COMPSIDE: BOT; DECOUPLER: NO; FPLIST: R0402; MEMORY: NO
R72 = R1K1%0402_0: COMPFIXED: NO; COMPGROUP: 0; COMPHEIGHT: 0.000; COMPKEY: NO; COMPLOC: [6042.000,4932.000]; COMPLOCKED: NO; COMPROT: 0; COMPSIDE: BOT; DECOUPLER: NO; FPLIST: R0402; MEMORY: NO
R73 = R1K1%0402_0: COMPFIXED: NO; COMPGROUP: 0; COMPHEIGHT: 0.000; COMPKEY: NO; COMPLOC: [5280.000,4938.000]; COMPLOCKED: NO; COMPROT: 180; COMPSIDE: BOT; DECOUPLER: NO; FPLIST: R0402; MEMORY: NO
R74 = R1K1%0402_0: COMPFIXED: NO; COMPGROUP: 0; COMPHEIGHT: 0.000; COMPKEY: NO; COMPLOC: [6042.000,4878.000]; COMPLOCKED: NO; COMPROT: 0; COMPSIDE: BOT; DECOUPLER: NO; FPLIST: R0402; MEMORY: NO
R75 = R1K1%0402_0: COMPFIXED: NO; COMPGROUP: 0; COMPHEIGHT: 0.000; COMPKEY: NO; COMPLOC: [5280.000,4884.000]; COMPLOCKED: NO; COMPROT: 180; COMPSIDE: BOT; DECOUPLER: NO; FPLIST: R0402; MEMORY: NO
R76 = R1K1%0402_0: COMPFIXED: NO; COMPGROUP: 0; COMPHEIGHT: 0.000; COMPKEY: NO; COMPLOC: [6042.000,4824.000]; COMPLOCKED: NO; COMPROT: 0; COMPSIDE: BOT; DECOUPLER: NO; FPLIST: R0402; MEMORY: NO
R77 = R1K1%0402_0: COMPFIXED: NO; COMPGROUP: 0; COMPHEIGHT: 0.000; COMPKEY: NO; COMPLOC: [5280.000,4830.000]; COMPLOCKED: NO; COMPROT: 180; COMPSIDE: BOT; DECOUPLER: NO; FPLIST: R0402; MEMORY: NO
R78 = R1K1%0402_0: COMPFIXED: NO; COMPGROUP: 0; COMPHEIGHT: 0.000; COMPKEY: NO; COMPLOC: [6042.000,4770.000]; COMPLOCKED: NO; COMPROT: 0; COMPSIDE: BOT; DECOUPLER: NO; FPLIST: R0402; MEMORY: NO
R79 = R1K1%0402_0: COMPFIXED: NO; COMPGROUP: 0; COMPHEIGHT: 0.000; COMPKEY: NO; COMPLOC: [5280.000,4776.000]; COMPLOCKED: NO; COMPROT: 180; COMPSIDE: BOT; DECOUPLER: NO; FPLIST: R0402; MEMORY: NO
R80 = R1K1%0402_0: COMPFIXED: NO; COMPGROUP: 0; COMPHEIGHT: 0.000; COMPKEY: NO; COMPLOC: [6042.000,4716.000]; COMPLOCKED: NO; COMPROT: 0; COMPSIDE: BOT; DECOUPLER: NO; FPLIST: R0402; MEMORY: NO
R82 = R1K1%0402_0: COMPFIXED: NO; COMPGROUP: 0; COMPHEIGHT: 0.000; COMPKEY: NO; COMPLOC: [6042.000,4662.000]; COMPLOCKED: NO; COMPROT: 0; COMPSIDE: BOT; DECOUPLER: NO; FPLIST: R0402; MEMORY: NO
R83 = R1K1%0402_0: COMPFIXED: NO; COMPGROUP: 0; COMPHEIGHT: 0.000; COMPKEY: NO; COMPLOC: [6042.000,4608.000]; COMPLOCKED: NO; COMPROT: 0; COMPSIDE: BOT; DECOUPLER: NO; FPLIST: R0402; MEMORY: NO
R87 = R1K1%0402_0: COMPFIXED: NO; COMPGROUP: 0; COMPHEIGHT: 0.000; COMPKEY: NO; COMPLOC: [6144.000,4386.000]; COMPLOCKED: NO; COMPROT: 0; COMPSIDE: BOT; DECOUPLER: NO; FPLIST: R0402; MEMORY: NO
R88 = R1K1%0402_0: COMPFIXED: NO; COMPGROUP: 0; COMPHEIGHT: 0.000; COMPKEY: NO; COMPLOC: [6144.000,4332.000]; COMPLOCKED: NO; COMPROT: 0; COMPSIDE: BOT; DECOUPLER: NO; FPLIST: R0402; MEMORY: NO
R89 = R1K1%0402_0: COMPFIXED: NO; COMPGROUP: 0; COMPHEIGHT: 0.000; COMPKEY: NO; COMPLOC: [5490.000,4338.000]; COMPLOCKED: NO; COMPROT: 180; COMPSIDE: BOT; DECOUPLER: NO; FPLIST: R0402; MEMORY: NO
R90 = R1K1%0402_0: COMPFIXED: NO; COMPGROUP: 0; COMPHEIGHT: 0.000; COMPKEY: NO; COMPLOC: [6144.000,4278.000]; COMPLOCKED: NO; COMPROT: 0; COMPSIDE: BOT; DECOUPLER: NO; FPLIST: R0402; MEMORY: NO
R91 = R1K1%0402_0: COMPFIXED: NO; COMPGROUP: 0; COMPHEIGHT: 0.000; COMPKEY: NO; COMPLOC: [5490.000,4284.000]; COMPLOCKED: NO; COMPROT: 180; COMPSIDE: BOT; DECOUPLER: NO; FPLIST: R0402; MEMORY: NO
R92 = R1K1%0402_0: COMPFIXED: NO; COMPGROUP: 0; COMPHEIGHT: 0.000; COMPKEY: NO; COMPLOC: [6144.000,4224.000]; COMPLOCKED: NO; COMPROT: 0; COMPSIDE: BOT; DECOUPLER: NO; FPLIST: R0402; MEMORY: NO
R93 = R1K1%0402_0: COMPFIXED: NO; COMPGROUP: 0; COMPHEIGHT: 0.000; COMPKEY: NO; COMPLOC: [5490.000,4230.000]; COMPLOCKED: NO; COMPROT: 180; COMPSIDE: BOT; DECOUPLER: NO; FPLIST: R0402; MEMORY: NO
R94 = R1K1%0402_0: COMPFIXED: NO; COMPGROUP: 0; COMPHEIGHT: 0.000; COMPKEY: NO; COMPLOC: [6144.000,4170.000]; COMPLOCKED: NO; COMPROT: 0; COMPSIDE: BOT; DECOUPLER: NO; FPLIST: R0402; MEMORY: NO
R95 = R1K1%0402_0: COMPFIXED: NO; COMPGROUP: 0; COMPHEIGHT: 0.000; COMPKEY: NO; COMPLOC: [5490.000,4176.000]; COMPLOCKED: NO; COMPROT: 180; COMPSIDE: BOT; DECOUPLER: NO; FPLIST: R0402; MEMORY: NO
R96 = R1K1%0402_0: COMPFIXED: NO; COMPGROUP: 0; COMPHEIGHT: 0.000; COMPKEY: NO; COMPLOC: [6144.000,4116.000]; COMPLOCKED: NO; COMPROT: 0; COMPSIDE: BOT; DECOUPLER: NO; FPLIST: R0402; MEMORY: NO
R97 = R1K1%0402_0: COMPFIXED: NO; COMPGROUP: 0; COMPHEIGHT: 0.000; COMPKEY: NO; COMPLOC: [6144.000,4062.000]; COMPLOCKED: NO; COMPROT: 0; COMPSIDE: BOT; DECOUPLER: NO; FPLIST: R0402; MEMORY: NO
R100 = R1K1%0402_0: COMPFIXED: NO; COMPGROUP: 0; COMPHEIGHT: 0.000; COMPKEY: NO; COMPLOC: [6144.000,4008.000]; COMPLOCKED: NO; COMPROT: 0; COMPSIDE: BOT; DECOUPLER: NO; FPLIST: R0402; MEMORY: NO
U2 U4 U10 = UTSV854IQ4T_4: COMPFIXED: NO; COMPGROUP: 0; COMPHEIGHT: 0.000; COMPKEY: NO; COMPLOC: [615.433,4410.333]; COMPLOCKED: NO; COMPROT: 0; COMPSIDE: BOT; DECOUPLER: NO; MEMORY: NO
U3 = UTSV854IQ4T_4: COMPFIXED: NO; COMPGROUP: 0; COMPHEIGHT: 0.000; COMPKEY: NO; COMPLOC: [3858.000,4536.000]; COMPLOCKED: NO; COMPROT: 0; COMPSIDE: BOT; DECOUPLER: NO; MEMORY: NO
U5 = UTSV854IQ4T_4: COMPFIXED: NO; COMPGROUP: 0; COMPHEIGHT: 0.000; COMPKEY: NO; COMPLOC: [1626.000,4494.000]; COMPLOCKED: NO; COMPROT: 0; COMPSIDE: BOT; DECOUPLER: NO; MEMORY: NO
U6 = UTSV854IQ4T_4: COMPFIXED: NO; COMPGROUP: 0; COMPHEIGHT: 0.000; COMPKEY: NO; COMPLOC: [2826.000,4416.000]; COMPLOCKED: NO; COMPROT: 0; COMPSIDE: BOT; DECOUPLER: NO; MEMORY: NO
U7 = UTSV854IQ4T_4: COMPFIXED: NO; COMPGROUP: 0; COMPHEIGHT: 0.000; COMPKEY: NO; COMPLOC: [4026.000,4404.000]; COMPLOCKED: NO; COMPROT: 0; COMPSIDE: BOT; DECOUPLER: NO; MEMORY: NO
U8 = UTSV854IQ4T_4: COMPFIXED: NO; COMPGROUP: 0; COMPHEIGHT: 0.000; COMPKEY: NO; COMPLOC: [5112.000,4392.000]; COMPLOCKED: NO; COMPROT: 0; COMPSIDE: BOT; DECOUPLER: NO; MEMORY: NO
U9 = UTSV854IQ4T_4: COMPFIXED: NO; COMPGROUP: 0; COMPHEIGHT: 0.000; COMPKEY: NO; COMPLOC: [5322.000,4392.000]; COMPLOCKED: NO; COMPROT: 0; COMPSIDE: BOT; DECOUPLER: NO; MEMORY: NO
U11 = UTSV854IQ4T_4: COMPFIXED: NO; COMPGROUP: 0; COMPHEIGHT: 0.000; COMPKEY: NO; COMPLOC: [2832.000,4200.000]; COMPLOCKED: NO; COMPROT: 90; COMPSIDE: BOT; DECOUPLER: NO; MEMORY: NO
U12 = UTSV854IQ4T_4: COMPFIXED: NO; COMPGROUP: 0; COMPHEIGHT: 0.000; COMPKEY: NO; COMPLOC: [4020.000,4122.000]; COMPLOCKED: NO; COMPROT: 0; COMPSIDE: BOT; DECOUPLER: NO; MEMORY: NO
U13 = UTSV854IQ4T_4: COMPFIXED: NO; COMPGROUP: 0; COMPHEIGHT: 0.000; COMPKEY: NO; COMPLOC: [5118.000,4092.000]; COMPLOCKED: NO; COMPROT: 0; COMPSIDE: BOT; DECOUPLER: NO; MEMORY: NO
U17 = 74LV4040_TSSOP_1: COMPFIXED: NO; COMPGROUP: 0; COMPHEIGHT: 0.000; COMPKEY: NO; COMPLOC: [1998.000,6090.000]; COMPLOCKED: NO; COMPROT: 270; COMPSIDE: BOT; DECOUPLER: NO; MEMORY: NO
U22 = 74hc4067_0: COMPFIXED: NO; COMPGROUP: 0; COMPHEIGHT: 0.000; COMPKEY: NO; COMPLOC: [2400.000,5963.383]; COMPLOCKED: NO; COMPROT: 90; COMPSIDE: BOT; DECOUPLER: NO; MEMORY: NO
U23 = 74hc4067_0: COMPFIXED: NO; COMPGROUP: 0; COMPHEIGHT: 0.000; COMPKEY: NO; COMPLOC: [1117.767,5901.617]; COMPLOCKED: NO; COMPROT: 90; COMPSIDE: BOT; DECOUPLER: NO; MEMORY: NO
U24 = 74hc4067_0: COMPFIXED: NO; COMPGROUP: 0; COMPHEIGHT: 0.000; COMPKEY: NO; COMPLOC: [5724.267,4862.117]; COMPLOCKED: NO; COMPROT: 90; COMPSIDE: BOT; DECOUPLER: NO; MEMORY: NO
U25 = 74hc4067_0: COMPFIXED: NO; COMPGROUP: 0; COMPHEIGHT: 0.000; COMPKEY: NO; COMPLOC: [5885.000,4285.000]; COMPLOCKED: NO; COMPROT: 90; COMPSIDE: BOT; DECOUPLER: NO; MEMORY: NO

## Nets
GND: C25.1 C25.2 C26.2 C28.2 C29.1 C29.2 C30.2 C31.2 C32.2 C33.2 C34.1 C34.2 C35.2 C36.2 C37.2 C38.2 C39.2 C40.2 C41.2 C42.2 C43.2 C44.2 C45.2 C46.2 C48.2 C49.2 C50.2 C51.2 C52.2 C55.2 C66.1 C66.2 C68.2 C76.2 C77.1 C77.2 C78.2 C89.2 C90.2 C99.2 C100.2 C109.2 C110.2 C111.2 C118.2 C119.2 C123.2 C124.2 C125.1 C125.2 C126.1 C126.2 C127.2 C128.1 C128.2 C129.2 C130.2 C131.2 C132.1 C132.2 C133.1 C133.2 C134.1 C134.2 C135.1 C135.2 C136.2 C137.2 C138.2 C139.1 C139.2 C140.2 C141.2 C142.1 C142.2 C143.2 C145.2 C147.1 C147.2 C148.2 C149.1 C149.2 C150.1 C150.2 C152.2 C153.2 C154.2 C155.1 C155.2 C156.2 C159.2 C160.2 C161.2 C162.2 C163.2 C170.1 L7.1 R7.1 R10.1 R12.1 R13.1 R15.1 R16.2 R17.1 R18.1 R107.1 R108.2 U2.2(VCC) U2.11(GND) U3.2(VCC) U3.11(GND) U4.1(IN+) U4.2(VCC) U4.9(IN+) U4.11(GND) U4.12(IN+) U5.2(VCC) U5.11(GND) U6.2(VCC) U6.11(GND) U7.2(VCC) U7.11(GND) U8.2(VCC) U8.11(GND) U9.2(VCC) U9.11(GND) U10.2(VCC) U10.11(GND) U11.2(VCC) U11.11(GND) U12.2(VCC) U12.11(GND) U13.2(VCC) U13.11(GND) U17.5(QD) U17.7(QB) U17.8(GND) U17.16(VCC) U22.1(OUT) U22.11(S1) U22.12(GND) U22.13(S3) U22.15(ENAL) U22.16(Y15) U22.24(VCC) U23.1(OUT) U23.11(S1) U23.12(GND) U23.13(S3) U23.15(ENAL) U23.16(Y15) U23.24(VCC) U24.11(S1) U24.12(GND) U24.13(S3) U24.15(ENAL) U24.24(VCC) U25.11(S1) U25.12(GND) U25.13(S3) U25.15(ENAL) U25.16(Y15) U25.24(VCC) U26.4(V-) U26.5(+INB) U27.4(V-) ; also on sheet 3
GND_AB: C1.2 D1.1(CATHODE) R1.2 R3.1 R112.1 U14.31(GND_B) U14.32(GND_A)
GND_CD: C2.2 D2.1(CATHODE) R2.2 R4.1 R111.1 U14.23(GND_D) U14.24(GND_C)
GND_POWER: C1.1 C2.1 C9.2 C10.2 C11.2 C12.2 C13.2 C14.2 C15.2 C16.2 C17.2 C18.2 C19.2 C20.1 C22.2 C47.2 C56.2 C57.2 D1.2(ANODE) D2.2(ANODE) D3.1(ANODE) HS1.1 HS1.2 HS1.3 HS1.4 R3.2 R4.2 R5.1 R6.2 R113.1 R115.1 U14.8(GND) U18.1(GND1) U18.2(GND2) U18.3(GND3) U18.5(~{ON}_OFF) U18.6(GND) ; also on sheet 3
P5VA: C152.1 C153.1 C154.1 C156.1 C159.1 C161.1 L7.2 U26.8(V+) U27.8(V+)
P12V: C9.1 C10.1 C19.1 C20.2 C56.1 C57.1 L6.2 R11.1 U14.1(GVDD_B) U14.17(VDD) U14.18(GVDD_C) U14.19(GVDD_D) U14.36(GVDD_A)
P48V: C11.1 C12.1 C13.1 C14.1 C15.1 C16.1 C17.1 C18.1 C22.1 U14.21(PVDD_D) U14.26(PVDD_C) U14.29(PVDD_B) U14.34(PVDD_A) U18.7(VIN) ; also on sheet 3
1: S1.1 S2.1 S3.1 S4.1 S5.1 S6.1 S7.1 S8.1 SO1.1 SO2.1 SO3.1 SO4.1 ; also on sheet 3
A0: U17.9(QA) U22.10(S0) U23.10(S0) U24.10(S0) U25.10(S0) ; also on sheet 3
A2: U17.6(QC) U22.14(S2) U23.14(S2) U24.14(S2) U25.14(S2) ; also on sheet 3
BRAKE1_VMON: U23.17(Y14) ; also on sheet 3
BRAKE2_VMON: U22.17(Y14) ; also on sheet 3
BRAKE3_VMON: U25.17(Y14) ; also on sheet 3
BRAKE4_VMON: U24.17(Y14) ; also on sheet 3
BST_A: C5.1 U14.35(BST_A)
BST_B: C6.1 U14.28(BST_B)
BST_C: C7.1 U14.27(BST_C)
BST_D: C8.2 U14.20(BST_D)
CLK: U17.10(~{CLK}) ; also on sheet 3
FAULTn: R9.1 U14.3(~{FAULT}) ; also on sheet 3
I_MOT+: C111.1 R81.2 U24.19(Y12)
I_MOT-: C124.1 R84.2 U24.18(Y13)
M1: R15.2 U14.13(M1)
M2: R14.1 U14.12(M2)
M3: R13.2 U14.11(M3)
OTWn: R8.1 U14.2(~{OTW}) ; also on sheet 3
OUT_A: C5.2 L1.1 U14.33(OUT_A)
OUT_B: C6.2 L2.1 U14.30(OUT_B)
OUT_C: C7.2 L3.1 U14.25(OUT_C)
OUT_D: C8.1 L4.1 U14.22(OUT_D)
PNET24_5: C4.1 R2.1
PNET24_6: C3.2 R1.1
POT3: U25.1(OUT) ; also on sheet 3
POT4: U24.1(OUT) ; also on sheet 3
PWM: R10.2 U14.4(PWM_A) ; also on sheet 3
PWMn: R12.2 U14.6(PWM_B) ; also on sheet 3
RESETn: R11.2 R17.2 R18.2 U14.5(~{RESET_AB}) U14.15(~{RESET_CD}) ; also on sheet 3
RST: U17.11(CLR) ; also on sheet 3
SJ1_POT2: U10.9(IN+) ; also on sheet 3
SJ1_POT3: U2.4(IN+) ; also on sheet 3
SJ1_POT5: U10.12(IN+) ; also on sheet 3
SJ1_POT6: U2.9(IN+) ; also on sheet 3
SJ1_POT12: U2.12(IN+) ; also on sheet 3
SJ1_POT13: U4.4(IN+) ; also on sheet 3
SJ1_POT14: U10.1(IN+) ; also on sheet 3
SJ1_POT15: U10.4(IN+) ; also on sheet 3
SJ1_POT16: U2.1(IN+) ; also on sheet 3
SJ1_POTF1: C55.1 R65.2 U23.9(Y0)
SJ1_POTF2: C52.1 R61.2 U23.8(Y1)
SJ1_POTF3: C49.1 R60.2 U23.7(Y2)
SJ1_POTF4: C45.1 R52.2 U23.6(Y3)
SJ1_POTF5: C44.1 R44.2 U23.5(Y4)
SJ1_POTF6: C37.1 R39.2 U23.4(Y5)
SJ1_POTF7: C33.1 R35.2 U23.3(Y6)
SJ1_POTF8: C30.1 R34.2 U23.2(Y7)
SJ1_POTF9: C38.1 R40.2 U23.23(Y8)
SJ1_POTF10: C39.1 R45.2 U23.22(Y9)
SJ1_POTF11: C46.1 R46.2 U23.21(Y10)
SJ1_POTF12: C50.1 R53.2 U23.20(Y11)
SJ1_SPARE1: U23.19(Y12) ; also on sheet 3
SJ1_SPARE2: U23.18(Y13) ; also on sheet 3
SJ2_POT1: U5.1(IN+) ; also on sheet 3
SJ2_POT2: U11.9(IN+) ; also on sheet 3
SJ2_POT3: U6.4(IN+) ; also on sheet 3
SJ2_POT4: U5.9(IN+) ; also on sheet 3
SJ2_POT5: U11.12(IN+) ; also on sheet 3
SJ2_POT6: U6.9(IN+) ; also on sheet 3
SJ2_POT11: U5.12(IN+) ; also on sheet 3
SJ2_POT12: U6.12(IN+) ; also on sheet 3
SJ2_POT13: U5.4(IN+) ; also on sheet 3
SJ2_POT14: U11.1(IN+) ; also on sheet 3
SJ2_POT15: U11.4(IN+) ; also on sheet 3
SJ2_POT16: U6.1(IN+) ; also on sheet 3
SJ2_POTF1: C51.1 R55.2 U22.9(Y0)
SJ2_POTF2: C48.1 R54.2 U22.8(Y1)
SJ2_POTF3: C41.1 R50.2 U22.7(Y2)
SJ2_POTF4: C40.1 R42.2 U22.6(Y3)
SJ2_POTF5: C35.1 R37.2 U22.5(Y4)
SJ2_POTF6: C31.1 R32.2 U22.4(Y5)
SJ2_POTF7: C28.1 R31.2 U22.3(Y6)
SJ2_POTF8: C26.1 R30.2 U22.2(Y7)
SJ2_POTF9: C32.1 R33.2 U22.23(Y8)
SJ2_POTF10: C36.1 R38.2 U22.22(Y9)
SJ2_POTF11: C42.1 R43.2 U22.21(Y10)
SJ2_POTF12: C43.1 R51.2 U22.20(Y11)
SJ2_SPARE1: U22.19(Y12) ; also on sheet 3
SJ2_SPARE2: U22.18(Y13) ; also on sheet 3
SJ3_POT1: U3.1(IN+) ; also on sheet 3
SJ3_POT2: U7.9(IN+) ; also on sheet 3
SJ3_POT3: U12.4(IN+) ; also on sheet 3
SJ3_POT4: U3.9(IN+) ; also on sheet 3
SJ3_POT5: U7.12(IN+) ; also on sheet 3
SJ3_POT6: U12.9(IN+) ; also on sheet 3
SJ3_POT11: U3.12(IN+) ; also on sheet 3
SJ3_POT12: U12.12(IN+) ; also on sheet 3
SJ3_POT13: U3.4(IN+) ; also on sheet 3
SJ3_POT14: U7.1(IN+) ; also on sheet 3
SJ3_POT15: U7.4(IN+) ; also on sheet 3
SJ3_POT16: U12.1(IN+) ; also on sheet 3
SJ3_POTF1: C148.1 R100.2 U25.9(Y0)
SJ3_POTF2: C145.1 R97.2 U25.8(Y1)
SJ3_POTF3: C143.1 R96.2 U25.7(Y2)
SJ3_POTF4: C140.1 R94.2 U25.6(Y3)
SJ3_POTF5: C137.1 R92.2 U25.5(Y4)
SJ3_POTF6: C136.1 R90.2 U25.4(Y5)
SJ3_POTF7: C129.1 R88.2 U25.3(Y6)
SJ3_POTF8: C127.1 R87.2 U25.2(Y7)
SJ3_POTF9: C130.1 R89.2 U25.23(Y8)
SJ3_POTF10: C131.1 R91.2 U25.22(Y9)
SJ3_POTF11: C138.1 R93.2 U25.21(Y10)
SJ3_POTF12: C141.1 R95.2 U25.20(Y11)
SJ3_SPARE1: U25.19(Y12) ; also on sheet 3
SJ3_SPARE2: U25.18(Y13) ; also on sheet 3
SJ4_LIFT_MOTOR+: C4.2 L3.2 L4.2 ; also on sheet 3
SJ4_LIFT_MOTOR-: C3.1 L1.2 L2.2 ; also on sheet 3
SJ4_POT1: U9.1(IN+) ; also on sheet 3
SJ4_POT2: U13.9(IN+) ; also on sheet 3
SJ4_POT3: U8.4(IN+) ; also on sheet 3
SJ4_POT4: U9.9(IN+) ; also on sheet 3
SJ4_POT5: U13.12(IN+) ; also on sheet 3
SJ4_POT6: U8.9(IN+) ; also on sheet 3
SJ4_POT11: U9.12(IN+) ; also on sheet 3
SJ4_POT12: U8.12(IN+) ; also on sheet 3
SJ4_POT13: U9.4(IN+) ; also on sheet 3
SJ4_POT14: U13.1(IN+) ; also on sheet 3
SJ4_POT15: U13.4(IN+) ; also on sheet 3
SJ4_POT16: U8.1(IN+) ; also on sheet 3
SJ4_POTF1: C123.1 R83.2 U24.9(Y0)
SJ4_POTF2: C119.1 R82.2 U24.8(Y1)
SJ4_POTF3: C118.1 R80.2 U24.7(Y2)
SJ4_POTF4: C109.1 R78.2 U24.6(Y3)
SJ4_POTF5: C99.1 R76.2 U24.5(Y4)
SJ4_POTF6: C89.1 R74.2 U24.4(Y5)
SJ4_POTF7: C76.1 R72.2 U24.3(Y6)
SJ4_POTF8: C68.1 R71.2 U24.2(Y7)
SJ4_POTF9: C78.1 R73.2 U24.23(Y8)
SJ4_POTF10: C90.1 R75.2 U24.22(Y9)
SJ4_POTF11: C100.1 R77.2 U24.21(Y10)
SJ4_POTF12: C110.1 R79.2 U24.20(Y11)
VA_BIAS: C160.1 C162.1 R114.2 R119.2 U24.16(Y15) U26.1(OUTA) U26.2(-INA)
VREG: C21.2 R8.2 R9.2 R14.2 U14.10(VREG)
N3819132: C170.2 R113.2 R119.1 U27.3(+INA)
N3819136: C158.1 R109.1 R111.2 U27.2(-INA)
N3819148: C158.2 R81.1 R109.2 U27.1(OUTA)
N3819830: C157.1 R110.1 R112.2 U27.6(-INB)
N3819870: C157.2 R84.1 R110.2 U27.7(OUTB)
N3819932: C163.1 R114.1 R115.2 U27.5(+INB)
N3820466: C21.1 R6.1 U14.9(AGND)
N3821182: R7.2 U14.16(PWM_D)
N3821198: R16.1 U14.14(PWM_C)
N3821898: R5.2 U14.7(OC_ADJ)
N3920893: C47.1 L5.2 L6.1 U18.4(FB)
N4096166: R107.2 R108.1 U26.3(+INA)
N5595023: U26.6(-INB) U26.7(OUTB)
N6692939: R35.1 U4.13(IN-) U4.14(OUT)
N6693001: R89.1 U3.5(IN-) U3.6(OUT)
N6693049: R94.1 U3.7(OUT) U3.8(IN-)
N6693089: R88.1 U3.13(IN-) U3.14(OUT)
N6693129: R91.1 U7.15(OUT) U7.16(IN-)
N6693173: R93.1 U7.5(IN-) U7.6(OUT)
N6693213: R51.1 U6.15(OUT) U6.16(IN-)
N6693217: R30.1 U6.13(IN-) U6.14(OUT)
N6693221: R97.1 U7.7(OUT) U7.8(IN-)
N6693293: R92.1 U7.13(IN-) U7.14(OUT)
N6693311: R100.1 U3.15(OUT) U3.16(IN-)
N6693321: R39.1 U2.7(OUT) U2.8(IN-)
N6693393: R95.1 U12.15(OUT) U12.16(IN-)
N6693431: R96.1 U12.5(IN-) U12.6(OUT)
N6693465: R90.1 U12.7(OUT) U12.8(IN-)
N6693509: R87.1 U12.13(IN-) U12.14(OUT)
N6693557: R40.1 U4.5(IN-) U4.6(OUT)
N6693601: R45.1 U10.15(OUT) U10.16(IN-)
N6693683: R52.1 U4.7(OUT) U4.8(IN-)
N6693747: R65.1 U4.15(OUT) U4.16(IN-)
N6693757: R73.1 U9.5(IN-) U9.6(OUT)
N6693797: R78.1 U9.7(OUT) U9.8(IN-)
N6693837: R72.1 U9.13(IN-) U9.14(OUT)
N6693887: R75.1 U13.15(OUT) U13.16(IN-)
N6693927: R77.1 U13.5(IN-) U13.6(OUT)
N6693931: R34.1 U2.13(IN-) U2.14(OUT)
N6693983: R82.1 U13.7(OUT) U13.8(IN-)
N6694061: R76.1 U13.13(IN-) U13.14(OUT)
N6694105: R83.1 U9.15(OUT) U9.16(IN-)
N6694159: R79.1 U8.15(OUT) U8.16(IN-)
N6694205: R80.1 U8.5(IN-) U8.6(OUT)
N6694213: R46.1 U10.5(IN-) U10.6(OUT)
N6694291: R74.1 U8.7(OUT) U8.8(IN-)
N6694359: R71.1 U8.13(IN-) U8.14(OUT)
N6694505: R33.1 U5.5(IN-) U5.6(OUT)
N6694569: R42.1 U5.7(OUT) U5.8(IN-)
N6694609: R31.1 U5.13(IN-) U5.14(OUT)
N6694661: R38.1 U11.15(OUT) U11.16(IN-)
N6694723: R43.1 U11.5(IN-) U11.6(OUT)
N6694749: R54.1 U11.7(OUT) U11.8(IN-)
N6694819: R37.1 U11.13(IN-) U11.14(OUT)
N6694859: R55.1 U5.15(OUT) U5.16(IN-)
N6695135: R50.1 U6.5(IN-) U6.6(OUT)
N6695209: R32.1 U6.7(OUT) U6.8(IN-)
N6695471: R61.1 U10.7(OUT) U10.8(IN-)
N6695607: R44.1 U10.13(IN-) U10.14(OUT)
N6695787: R53.1 U2.15(OUT) U2.16(IN-)
N6695799: R60.1 U2.5(IN-) U2.6(OUT)
N7118838: D3.3(CATHODE) L5.1 U18.8(VOUT)

Not connected (* = marked no-connect by the designer): U17 1(QL) 2(QF) 3(QE) 4(QG) 12(QI) 13(QH) 14(QJ) 15(QK)

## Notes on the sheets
sheet 1
- keep feedback path away from inductor flux
- Motor Driver
- 0.636V @ 5.3A peak Motor Current
- OVER-CURRENT THRESHOLD:
- STUFFED
- PCA SPEC:
  9.2A +/- 25%
- ACTUAL DESIGN:
  9.2A +/- 21%
- Use 4-wire termination on sense resistors.
- ON HEATSINK
